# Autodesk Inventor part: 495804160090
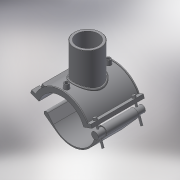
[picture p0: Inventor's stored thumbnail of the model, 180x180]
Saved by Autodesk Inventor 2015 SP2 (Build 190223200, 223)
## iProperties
Created: 2017-07
Part Number: 495804160090
Material: Generic
Description: PLASSON BRANCH SADDLE 160-90
Document SubType Name: Modeling
Designer: KIM
Density: 1 g/cm^3
Appearance: Default
Author: KIM
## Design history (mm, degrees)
derived "495804.ipt"
feature "Solid1::495804.ipt"
feature "Solid2::495804.ipt"
tag "TaggingFeature1"
body "Solid1"
body "Solid2"
other parameters: "d2" = 228.8, "d4" = 176, "d5" = 0, "d6" = 0.1, "d8" = 0, "d19" = 6, "d20" = 6, "d21" = 105.6, "d23" = 0, "d24" = 52.8, "d26" = 0, "d27" = 3, "d28" = 3, "d29" = 3, "d30" = 53.33333, "d31" = 6, "d32" = 0, "d33" = 0, "d34" = 0.6, "d40" = 98.8, "d41" = 99, "d43" = 0, "d45" = 0, "d50" = 0, "d70" = 15, "d72" = 0, "d73" = 6, "d75" = 5, "d76" = 0, "d77" = 8, "d79" = 15, "d80" = 70.4, "d82" = 5 deg, "d84" = 4, "d85" = 14, "d86" = 0, "d87" = 3, "d88" = 0, "d89" = 1, "d90" = 1, "d91" = 140.8, "d92" = 0, "d93" = 0.5, "d94" = 84.21053, "d96" = 193.8, "d97" = 3.52, "d98" = 0, "d102" = 2.7, "d103" = 72, "d105" = 0, "d109" = -35, "d117" = 0.9, "d120" = 140 deg, "d121" = 24.228, "d122" = 20 deg, "d124" = 114, "d126" = 0, "d143" = 168, "d150" = 28.8, "d159" = 6, "d161" = 4, "d162" = 105.6, "d163" = 0, "d167" = 32, "d168" = 86.36364, "d173" = 1, "d176" = 20 deg, "d177" = 11.2, "d180" = 0, "d185" = 57.2, "d186" = 57.2, "d187" = 95, "d188" = 9, "d189" = 11.2, "d190" = 0, "d191" = 142.5, "d200" = 15, "d202" = 0, "d216" = 158.4, "d217" = 0, "d221" = 65.12, "d222" = 11.2, "d223" = 6.72, "d225" = 6.72, "d227" = 23.04, "d230" = 104, "d236" = 20 deg, "d237" = 102, "d238" = 20 deg, "d239" = 11.2, "B_" = 176, "H_" = 105, "L_" = 176, "d_t" = 6, "d148" = 4, "d160" = 4
